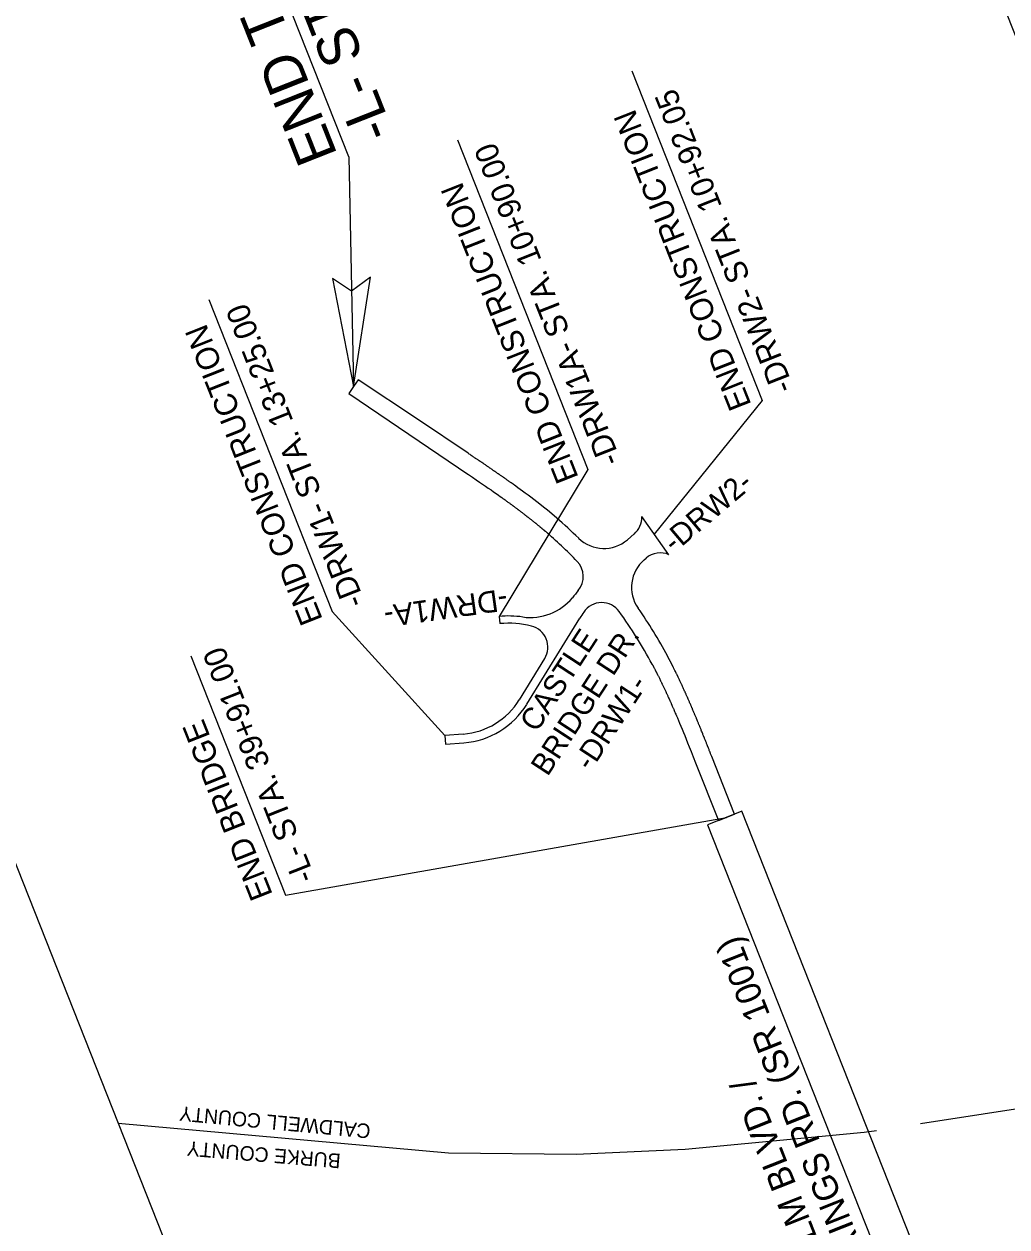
# Model space of a CAD drawing. Extents: x 1247235 to 1260080, y 742320 to 754020.
# Drawn here: x 1250042 to 1251398, y 748232 to 749890 of the extents above; entities that cross this region are included whole.
import ezdxf

# ---------------------------------------------------------------- set-up
doc = ezdxf.new("R2010")
doc.units = 0
for name, color, linetype in [('Exist Boundary County Line', 7, 'Continuous'), ('Exist Boundary County Line Text', 7, 'Continuous'), ('Prop DSN Text', 7, 'Continuous'), ('Prop Horizontal Alignment Direction Label', 7, 'Continuous'), ('Prop Shade Heavy', 7, 'Continuous'), ('Prop Shade Medium', 7, 'Continuous'), ('Prop Terminator CELL', 7, 'Continuous'), ('Scratch_Level_3', 7, 'Continuous')]:
    doc.layers.add(name, color=color, linetype=linetype)

msp = doc.modelspace()

# ---------------------------------------------------------------- linework, layer by layer
at = {"layer": 'Exist Boundary County Line'}
for points in [[(1251957.1, 748487.6), (1251716.2, 748441.3), (1251278.4, 748373.7)], [(1251217.6, 748364.3), (1251200.5, 748361.6), (1250953.9, 748338.5), (1250803.6, 748331.5), (1250627.6, 748333.1), (1250172.3, 748374.3)]]:
    msp.add_lwpolyline(points, dxfattribs=at)
at = {"layer": 'Prop DSN Text'}
for p, q in [((1250880.4, 749825.2), (1251060.2, 749370.5)), ((1250640, 749730.1), (1250819.8, 749275.4)), ((1250297, 749510.1), (1250467.1, 749079.9)), ((1250272.4, 749018.9), (1250402.9, 748688.7))]:
    msp.add_line(p, q, dxfattribs=at)
for points in [[(1251060.2, 749370.5), (1250911.2, 749186.6)], [(1250819.8, 749275.4), (1250697.4, 749073.2)], [(1250467.1, 749079.9), (1250622.6, 748908.9)], [(1250402.9, 748688.7), (1251010.8, 748796)]]:
    msp.add_lwpolyline(points, dxfattribs=at)
at = {"layer": 'Prop Horizontal Alignment Direction Label'}
msp.add_line((1250490.3, 749706.7), (1250080.1, 750744.2), dxfattribs=at)
msp.add_lwpolyline([(1250490.3, 749706.7), (1250496.5, 749390)], dxfattribs=at)
at = {"layer": 'Prop Shade Heavy'}
for p, q in [((1250999.7, 748791.6), (1250984.8, 748785.7)), ((1251022, 748800.5), (1250999.7, 748791.6)), ((1251032.2, 748804.5), (1251022, 748800.5)), ((1251428.2, 747803), (1251032.2, 748804.5)), ((1250984.8, 748785.7), (1251380.8, 747784.2))]:
    msp.add_line(p, q, dxfattribs=at)
at = {"layer": 'Prop Shade Medium'}
for p, q in [((1250496.5, 749390), (1250490.1, 749380.5)), ((1250502.8, 749399.4), (1250496.5, 749390)), ((1250586.1, 749344.1), (1250502.8, 749399.4)), ((1250490.1, 749380.5), (1250572.7, 749324.2)), ((1250654.6, 749297.9), (1250586.1, 749344.1)), ((1250572.7, 749324.2), (1250641.2, 749278)), ((1250931.5, 749158.1), (1250894.1, 749210.6)), ((1250883.5, 749186.7), (1250874.2, 749178.7)), ((1250897.5, 749151.3), (1250900.1, 749153.5)), ((1250798.5, 749098.7), (1250798.4, 749098.8)), ((1250697.4, 749073.2), (1250698.3, 749063.2)), ((1250735.4, 748952), (1250808.5, 749070.8)), ((1250760.1, 749015), (1250725.2, 748958.2)), ((1250908.3, 749007.2), (1250908.3, 749007.2)), ((1250648, 748911), (1250622.6, 748908.9)), ((1250622.6, 748908.9), (1250623.5, 748897)), ((1250623.5, 748897), (1250648.9, 748899)), ((1251022, 748800.5), (1250990.5, 748880.1)), ((1250968.2, 748871.3), (1250999.7, 748791.6)), ((1250999.7, 748791.6), (1251022, 748800.5))]:
    msp.add_line(p, q, dxfattribs=at)
for points in [[(1250776.7, 749208.6), (1250776.7, 749208.6)], [(1250761.1, 749190.4), (1250761.1, 749190.4)], [(1250807, 749181), (1250807, 749181)], [(1250888.9, 749084.6), (1250888.9, 749084.6)], [(1250908.3, 749007.2), (1250908.3, 749007.2)], [(1250908.3, 749007.2), (1250908.3, 749007.2)], [(1250929.5, 749018.5), (1250929.5, 749018.6)], [(1250924.9, 748974.3), (1250924.9, 748974.2)], [(1250932.1, 748958.5), (1250932.1, 748958.5)]]:
    msp.add_lwpolyline(points, dxfattribs=at)
for centre, radius, start, end in [((1250346, 748705.9), 662, 45.8597, 49.4104), ((1250864.1, 749209.5), 30, 310.3793, 2.0969), ((1250346, 748705.9), 638, 49.4095, 49.4104), ((1250346, 748705.9), 638, 43.988, 49.4095), ((1250841.8, 749216.8), 50, 225.86, 310.3793), ((1250919.5, 749130.7), 30, 66.3998, 130.3793), ((1250783.4, 749128.1), 30, 320.2515, 43.988), ((1250929.9, 749113.2), 50, 130.3793, 214.8986), ((1250977.2, 748967), 222, 140.2515, 143.6028), ((1250740.6, 749146.6), 75, 261.8578, 320.425), ((1250838.7, 749062.1), 30, 35.867, 145.5216), ((1250710.1, 748933.7), 140, 81.8578, 95.2341), ((1250977.2, 748967), 198, 145.5216, 148.4011), ((1250346, 748705.9), 638, 28.1862, 35.867), ((1250346, 748705.9), 662, 28.1854, 34.8989), ((1250710.1, 748933.7), 130, 75.8587, 95.2341), ((1250734.6, 749030.7), 30, 328.4011, 75.8587), ((1250346, 748705.9), 638, 28.1854, 28.1862), ((1250640, 749010.6), 100, 274.5565, 328.4011), ((1250640, 749010.6), 112, 274.5565, 328.4011)]:
    msp.add_arc(centre, radius, start, end, dxfattribs=at)
for points, degree in [([(1250716.6, 749255.2), (1250715.4, 749256.1), (1250714.1, 749257.1), (1250712.2, 749258.4), (1250711.5, 749258.9), (1250710.2, 749259.8), (1250709.6, 749260.3), (1250707.7, 749261.6), (1250706.4, 749262.5), (1250704.8, 749263.7), (1250704.4, 749263.9), (1250703.8, 749264.3), (1250702.8, 749265), (1250701.9, 749265.7), (1250699.9, 749267), (1250698.6, 749267.9), (1250696, 749269.7), (1250694.4, 749270.8), (1250692.8, 749272), (1250692.2, 749272.4), (1250691.8, 749272.6), (1250690.9, 749273.3), (1250690.2, 749273.7), (1250688.3, 749275.1), (1250687, 749276), (1250684.4, 749277.7), (1250683.1, 749278.6), (1250681.2, 749280), (1250680.5, 749280.4), (1250679.2, 749281.3), (1250678.6, 749281.7), (1250676.6, 749283), (1250674.7, 749284.4), (1250672.7, 749285.7), (1250671.8, 749286.3), (1250671.4, 749286.6), (1250670.8, 749287), (1250670.5, 749287.2), (1250668.8, 749288.3), (1250667.5, 749289.2), (1250665.6, 749290.5), (1250664.9, 749290.9), (1250663.6, 749291.8), (1250662.3, 749292.7), (1250661.1, 749293.6), (1250660.1, 749294.2), (1250659.8, 749294.4), (1250659.1, 749294.9), (1250657.5, 749296), (1250655.9, 749297.1), (1250654.6, 749297.9)], 3), ([(1250641.2, 749278), (1250661.9, 749264), (1250682.5, 749250.2), (1250702.6, 749235.8), (1250702.7, 749235.7)], 3), ([(1250776.7, 749208.6), (1250757.6, 749224.9), (1250737.4, 749240.3), (1250716.7, 749255.2), (1250716.6, 749255.2)], 3), ([(1250702.7, 749235.7), (1250705.2, 749233.9), (1250707.7, 749232.1), (1250711.4, 749229.4), (1250712.7, 749228.5), (1250714.5, 749227.1), (1250715.2, 749226.6), (1250716.4, 749225.7), (1250717, 749225.3), (1250718.9, 749223.9), (1250720.1, 749223), (1250722, 749221.6), (1250722.6, 749221.1), (1250723.8, 749220.2), (1250724.5, 749219.7), (1250726.3, 749218.3), (1250727.5, 749217.4), (1250729.4, 749216), (1250730, 749215.5), (1250731.2, 749214.6), (1250733, 749213.2), (1250734.9, 749211.7), (1250736.7, 749210.3), (1250737.3, 749209.8), (1250738.5, 749208.9), (1250739.1, 749208.4), (1250740.9, 749207), (1250742.1, 749206), (1250744.5, 749204.1), (1250745.7, 749203.1), (1250747.5, 749201.7), (1250748.1, 749201.2), (1250749.3, 749200.2), (1250749.9, 749199.7), (1250751.7, 749198.3), (1250752.8, 749197.3), (1250754.3, 749196.1), (1250754.6, 749195.8), (1250755.2, 749195.3), (1250755.5, 749195.1), (1250756.4, 749194.3), (1250757.1, 749193.7), (1250757.9, 749193.1), (1250758, 749193), (1250758, 749193), (1250758, 749192.9), (1250758.1, 749192.9), (1250758.1, 749192.9), (1250758.3, 749192.8), (1250758.4, 749192.7), (1250758.7, 749192.4), (1250759, 749192.1), (1250759.4, 749191.8), (1250759.4, 749191.8), (1250759.5, 749191.7), (1250759.5, 749191.7), (1250759.5, 749191.7), (1250759.5, 749191.7), (1250759.5, 749191.7), (1250759.5, 749191.7), (1250759.6, 749191.6), (1250759.6, 749191.6), (1250759.8, 749191.4), (1250760.3, 749191), (1250760.8, 749190.6), (1250761.1, 749190.4)], 3), ([(1250761.1, 749190.4), (1250761.1, 749190.4), (1250761.1, 749190.4), (1250761.1, 749190.4)], 2), ([(1250908.3, 749007.2), (1250908.3, 749007.2), (1250908.3, 749007.2), (1250908.3, 749007.2)], 2), ([(1250908.3, 749007.2), (1250908.5, 749006.9), (1250908.8, 749006.4), (1250909, 749005.9), (1250909.1, 749005.7)], 3), ([(1250936.1, 749005.9), (1250934.1, 749009.8), (1250931.8, 749014.2), (1250929.5, 749018.5)], 2), ([(1250909.1, 749005.7), (1250909.1, 749005.7), (1250909.1, 749005.7), (1250909.2, 749005.6), (1250909.2, 749005.5), (1250909.2, 749005.5), (1250909.2, 749005.5), (1250909.2, 749005.5), (1250909.2, 749005.5), (1250909.3, 749005.4), (1250909.3, 749005.4), (1250909.3, 749005.4), (1250909.3, 749005.3), (1250909.6, 749004.9), (1250909.7, 749004.5), (1250910, 749004.1), (1250910, 749004), (1250910.1, 749003.9), (1250910.1, 749003.8)], 3), ([(1250910.1, 749003.8), (1250910.1, 749003.8), (1250910.1, 749003.8), (1250910.1, 749003.8), (1250910.1, 749003.8)], 3), ([(1250910.1, 749003.8), (1250910.2, 749003.7), (1250910.2, 749003.7), (1250910.2, 749003.7), (1250910.2, 749003.7), (1250910.2, 749003.7), (1250910.2, 749003.7), (1250910.2, 749003.7)], 3), ([(1250910.2, 749003.7), (1250910.2, 749003.7), (1250910.3, 749003.5), (1250910.4, 749003.3), (1250911.2, 749001.8), (1250911.9, 749000.4), (1250912.8, 748998.7), (1250912.9, 748998.4), (1250913.3, 748997.7), (1250913.6, 748997.2), (1250913.9, 748996.6), (1250914, 748996.4)], 3), ([(1250914, 748996.4), (1250914.2, 748995.9), (1250914.5, 748995.5), (1250914.8, 748994.8), (1250914.9, 748994.5), (1250915, 748994.3)], 3), ([(1250915, 748994.3), (1250915.1, 748994.2), (1250915.2, 748994.1), (1250915.4, 748993.6), (1250915.9, 748992.6), (1250916.4, 748991.6), (1250917.5, 748989.5), (1250918.2, 748988.1), (1250919.5, 748985.4), (1250920.4, 748983.6), (1250921.2, 748981.9), (1250921.5, 748981.2), (1250921.7, 748980.9), (1250922.2, 748979.8), (1250922.5, 748979.1), (1250923.5, 748977), (1250924.2, 748975.7), (1250924.9, 748974.3)], 3), ([(1250962.1, 748949.9), (1250961.8, 748950.6), (1250961.5, 748951.4), (1250960.9, 748952.8), (1250960.5, 748953.5), (1250959.6, 748955.7), (1250959, 748957.2), (1250958, 748959.3), (1250957.7, 748960), (1250957.1, 748961.5), (1250956.7, 748962.2), (1250955.8, 748964.4), (1250955.1, 748965.8), (1250954.3, 748967.6), (1250954.2, 748968), (1250953.8, 748968.7), (1250953.7, 748969.1), (1250953.2, 748970.1), (1250952.2, 748972.3), (1250951.2, 748974.5), (1250950.2, 748976.6), (1250949.9, 748977.3), (1250949.2, 748978.8), (1250948.9, 748979.5), (1250947.9, 748981.6), (1250947.2, 748983.1), (1250945.9, 748985.9), (1250945.2, 748987.4), (1250944.2, 748989.5), (1250943.8, 748990.2), (1250943.3, 748991.3), (1250943.1, 748991.7), (1250942.8, 748992.4), (1250941.9, 748994.2), (1250941.1, 748995.9), (1250939.6, 748998.8), (1250938.9, 749000.2), (1250937.9, 749002.3), (1250937.3, 749003.4), (1250936.8, 749004.5), (1250936.4, 749005.2), (1250936.3, 749005.5), (1250936.1, 749005.9), (1250936.1, 749005.9), (1250936.1, 749005.9)], 3), ([(1250924.9, 748974.2), (1250925.5, 748972.8), (1250926.2, 748971.4), (1250927.1, 748969.4), (1250927.5, 748968.7), (1250928.1, 748967.3), (1250928.4, 748966.6), (1250929.4, 748964.5), (1250930.1, 748963), (1250930.7, 748961.6), (1250930.7, 748961.6)], 3), ([(1250930.7, 748961.6), (1250931, 748960.9), (1250931.3, 748960.2), (1250931.7, 748959.4), (1250931.8, 748959.2), (1250931.9, 748959)], 3), ([(1250931.9, 748959), (1250932, 748958.9), (1250932, 748958.7), (1250932.1, 748958.5), (1250932.1, 748958.5), (1250932.1, 748958.5)], 3), ([(1250932.1, 748958.5), (1250932.3, 748958.1), (1250932.4, 748957.8), (1250933.2, 748956), (1250933.9, 748954.6), (1250934.8, 748952.5), (1250935.1, 748951.8), (1250935.7, 748950.4), (1250936, 748949.7), (1250937, 748947.5), (1250937.6, 748946.1), (1250938.5, 748944), (1250938.8, 748943.3), (1250939.4, 748941.9), (1250939.7, 748941.2), (1250940, 748940.4)], 3), ([(1250990.5, 748880.1), (1250989.9, 748881.6), (1250989.3, 748883), (1250988.6, 748884.8), (1250988.5, 748885.2), (1250988.2, 748885.9), (1250988, 748886.3), (1250987.6, 748887.4), (1250986.7, 748889.6), (1250985.9, 748891.8), (1250985.2, 748893.6), (1250985, 748893.9), (1250984.7, 748894.7), (1250984.3, 748895.8), (1250983.9, 748896.8), (1250983, 748899), (1250982.4, 748900.5), (1250981.2, 748903.4), (1250980.7, 748904.8), (1250979.9, 748906.7), (1250979.8, 748907), (1250979.5, 748907.8), (1250979.4, 748908.1), (1250978.9, 748909.2), (1250978, 748911.4), (1250977.2, 748913.6), (1250976, 748916.5), (1250975.4, 748918), (1250974.5, 748920.1), (1250974.2, 748920.9), (1250973.6, 748922.3), (1250973.3, 748923), (1250972.4, 748925.2), (1250971.8, 748926.7), (1250970.9, 748928.9), (1250970.6, 748929.6), (1250970.2, 748930.7), (1250970, 748931), (1250969.7, 748931.8), (1250969, 748933.6), (1250968.2, 748935.4), (1250967.3, 748937.6), (1250967, 748938.3), (1250966.4, 748939.8), (1250965.5, 748941.9), (1250964.6, 748944.1), (1250963.7, 748946.3), (1250963.3, 748947), (1250962.7, 748948.5), (1250962.4, 748949.2), (1250962.1, 748949.9)], 3), ([(1250940, 748940.4), (1250940.1, 748940.4), (1250949.9, 748917.6), (1250959, 748894.6), (1250968.2, 748871.3)], 3)]:
    msp.add_open_spline(points, degree=degree, dxfattribs=at)
at = {"layer": 'Prop Terminator CELL'}
msp.add_lwpolyline([(1250467.8, 749539), (1250496.5, 749390), (1250520.1, 749540.8), (1250493.9, 749521.2)], close=True, dxfattribs=at)
at = {"layer": 'Scratch_Level_3'}
msp.add_lwpolyline([(1251095.3, 746040.1), (1249533.8, 749989.2), (1251115.9, 750614.8), (1252677.6, 746665.7)], close=True, dxfattribs=at)

# ---------------------------------------------------------------- texts
at = {"layer": 'Exist Boundary County Line Text'}
for s, rotation, p in [('CALDWELL COUNTY', 174.6323, (1250520.9, 748373.3)), ('BURKE COUNTY', 175.2569, (1250479.6, 748332.2))]:
    msp.add_text(s, height=20, rotation=rotation, dxfattribs=at).set_placement(p)
at = {"layer": 'Prop DSN Text'}
for s, height, rotation, p in [('END TIP PROJECT R-3430B', 56.25, 111.5743, (1250474.9, 749709.4)), ('-L- STA. 48+00.00', 56.25, 111.5743, (1250552.3, 749740)), ('-DRW2- STA. 10+92.05', 31.5, 111.5743, (1251104.1, 749388)), ('END CONSTRUCTION', 31.5, 111.5743, (1251045.5, 749364.9)), ('-DRW1A- STA. 10+90.00', 31.5, 111.5743, (1250865.7, 749287.7)), ('END CONSTRUCTION', 31.5, 111.5743, (1250807.2, 749264.5)), ('-DRW1- STA. 13+25.00', 31.5, 111.5743, (1250513, 749092.2)), ('END CONSTRUCTION', 31.5, 111.5743, (1250454.5, 749069)), ('-DRW2-', 30, 40.2181, (1250938.6, 749159.9)), ('-DRW1A-', 30, 188.0254, (1250706.9, 749111.5)), ('CASTLE ', 30, 56.8101, (1250749.1, 748912)), ('BRIDGE DR.', 30, 56.8101, (1250764.2, 748851.5)), ('-L- STA. 39+91.00', 31.5, 111.5743, (1250444.2, 748712.8)), ('-DRW1-', 30, 56.8101, (1250823.6, 748858.8)), ('END BRIDGE', 31.5, 111.5743, (1250385.6, 748689.6)), ('CONNELLY SPRINGS RD. (SR 1001)', 35, 111.5755, (1251320.1, 747895)), ('-L- MALCOLM BLVD. /', 35, 111.5755, (1251223.1, 747997.6))]:
    msp.add_text(s, height=height, rotation=rotation, dxfattribs=at).set_placement(p)

doc.saveas('drawing.dxf')
